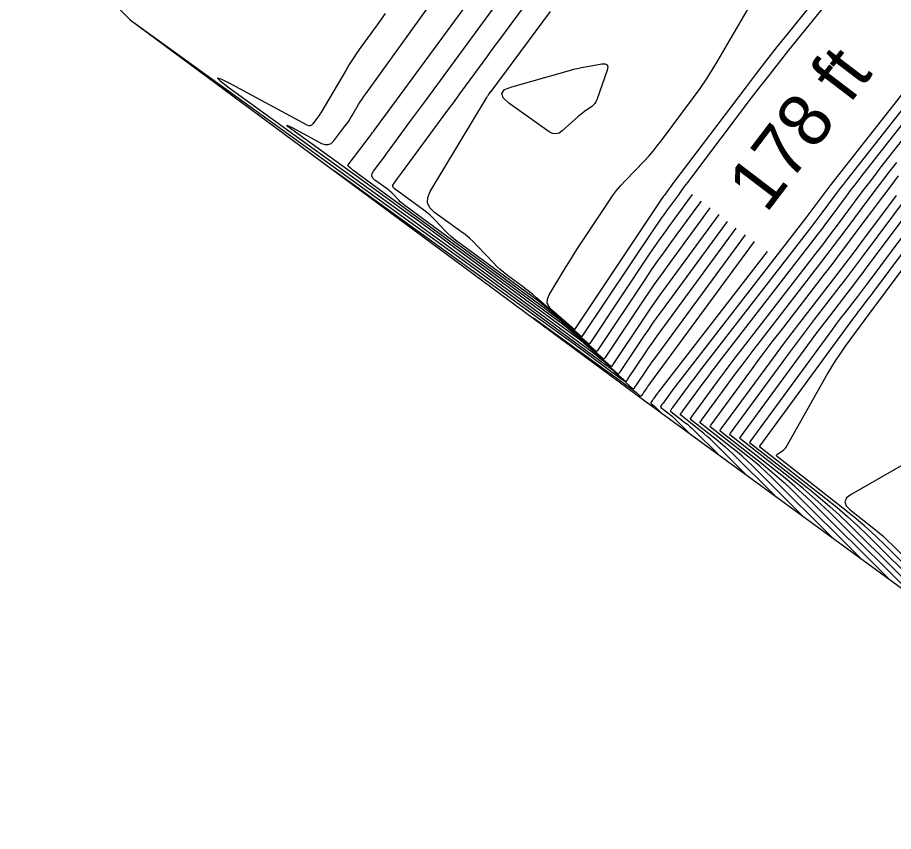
# Model space of a CAD drawing. Extents: x 7585033 to 7595090, y 547091 to 553471.
# Drawn here: x 7586349.7 to 7586454.1, y 547283 to 547380 of the extents above; entities that cross this region are included whole.
import ezdxf

# ---------------------------------------------------------------- set-up
doc = ezdxf.new("R2010")
doc.units = 0
for name, color, linetype in [('E_TERR_BNDRY_Perimeter', 7, 'Continuous'), ('E_TERR_DSPLAY_GeneralTx', 7, 'Continuous'), ('E_TERR_DSPLAY_MajContour', 7, 'Continuous'), ('E_TERR_DSPLAY_MinContour', 7, 'Continuous')]:
    doc.layers.add(name, color=color, linetype=linetype)

msp = doc.modelspace()

# ---------------------------------------------------------------- linework, layer by layer
at = {"layer": 'E_TERR_BNDRY_Perimeter'}
msp.add_lwpolyline([(7586507.86, 547596.21), (7586495.55, 547580.23), (7586483.33, 547564.27), (7586468.31, 547544.88), (7586458.94, 547532.34), (7586446.63, 547516.23), (7586434.88, 547500.79), (7586392.64, 547487.4), (7586380.44, 547481.39), (7586375.31, 547475.38), (7586349.66, 547424.97), (7586351.68, 547391.19), (7586363.11, 547379.7), (7586424.46, 547334.33), (7586496.39, 547281.87), (7586525.63, 547263.53), (7586582.63, 547204.01), (7586615.09, 547187.11), (7586630.91, 547181.81), (7586662.02, 547163.71), (7586688.76, 547131.86)], dxfattribs=at)
at = {"layer": 'E_TERR_DSPLAY_MajContour'}
for points in [[(7586436.55, 547325.51), (7586432.64, 547329.38), (7586432.27, 547329.74), (7586431.89, 547330.08), (7586431.5, 547330.42), (7586431.1, 547330.74), (7586428.73, 547332.59), (7586428.7, 547332.62), (7586428.69, 547332.65), (7586428.69, 547332.69), (7586428.71, 547332.72), (7586428.81, 547332.87), (7586428.84, 547332.9), (7586428.87, 547332.94), (7586428.89, 547332.97), (7586428.92, 547333.01), (7586431.54, 547336.58), (7586431.99, 547337.19), (7586432.44, 547337.79), (7586432.9, 547338.39), (7586433.35, 547338.99), (7586444.54, 547353.43), (7586445.04, 547354.08), (7586445.54, 547354.74), (7586446.03, 547355.4), (7586446.53, 547356.06), (7586448.5, 547358.7), (7586448.99, 547359.36), (7586449.49, 547360.01), (7586449.99, 547360.67), (7586450.5, 547361.32), (7586470.52, 547386.8)], [(7586430.11, 547358.9), (7586429.55, 547358.15), (7586427.28, 547355.04), (7586426.71, 547354.26), (7586426.15, 547353.48), (7586425.6, 547352.68), (7586425.06, 547351.89), (7586417.88, 547341.16), (7586417.87, 547341.14), (7586417.86, 547341.13), (7586417.85, 547341.12), (7586417.85, 547341.1), (7586417.81, 547341.05), (7586417.8, 547341.04), (7586417.79, 547341.04), (7586417.78, 547341.04), (7586417.76, 547341.05), (7586413.7, 547344.6), (7586413.01, 547345.19), (7586412.31, 547345.76), (7586411.6, 547346.32), (7586410.87, 547346.87), (7586402.05, 547353.35), (7586401.69, 547353.62), (7586401.35, 547353.91), (7586401.02, 547354.22), (7586400.7, 547354.54), (7586399.46, 547355.85), (7586399.15, 547356.17), (7586398.81, 547356.47), (7586398.47, 547356.76), (7586398.11, 547357.03), (7586394.58, 547359.59), (7586394.45, 547359.71), (7586394.4, 547359.84), (7586394.41, 547359.99), (7586394.5, 547360.14), (7586394.98, 547360.79), (7586395.1, 547360.95), (7586395.22, 547361.11), (7586395.34, 547361.27), (7586395.46, 547361.43), (7586400.42, 547368.18), (7586401.08, 547369.09), (7586401.75, 547369.99), (7586402.41, 547370.89), (7586403.07, 547371.79), (7586405.72, 547375.4), (7586406.39, 547376.31), (7586407.05, 547377.21), (7586407.72, 547378.11), (7586408.38, 547379.01), (7586411.83, 547383.66)], [(7586393.49, 547380.46), (7586393.01, 547379.79), (7586392.53, 547379.12), (7586390.6, 547376.44), (7586390.12, 547375.76), (7586389.66, 547375.08), (7586389.22, 547374.38), (7586388.79, 547373.68), (7586385.81, 547368.62), (7586385.7, 547368.45), (7586385.59, 547368.27), (7586385.47, 547368.1), (7586385.34, 547367.94), (7586384.83, 547367.28), (7586384.7, 547367.15), (7586384.55, 547367.08), (7586384.39, 547367.08), (7586384.21, 547367.15), (7586375.13, 547372.02), (7586373.93, 547372.63), (7586373.49, 547372.77), (7586373.81, 547372.43), (7586374.88, 547371.62), (7586396.17, 547356.26), (7586398.44, 547354.62), (7586400.7, 547352.97), (7586402.96, 547351.32), (7586405.22, 547349.67), (7586418.06, 547340.23), (7586418.4, 547339.97), (7586418.74, 547339.71), (7586419.06, 547339.44), (7586419.39, 547339.16), (7586421.25, 547337.53), (7586421.28, 547337.51), (7586421.31, 547337.51), (7586421.34, 547337.52), (7586421.36, 547337.55), (7586421.46, 547337.68), (7586421.49, 547337.71), (7586421.51, 547337.74), (7586421.53, 547337.78), (7586421.56, 547337.81), (7586424.43, 547342.1), (7586424.92, 547342.83), (7586425.42, 547343.55), (7586425.92, 547344.26), (7586426.44, 547344.97), (7586434.31, 547355.69)], [(7586462.59, 547361.93), (7586451.62, 547347.2), (7586451.43, 547346.95), (7586451.24, 547346.7), (7586451.05, 547346.45), (7586450.86, 547346.2), (7586450.09, 547345.2), (7586449.9, 547344.95), (7586449.71, 547344.7), (7586449.52, 547344.45), (7586449.33, 547344.2), (7586438.13, 547328.92), (7586438.11, 547328.89), (7586438.11, 547328.88), (7586438.11, 547328.88), (7586438.11, 547328.88), (7586438.11, 547328.88), (7586446.03, 547322.68), (7586447.33, 547321.63), (7586448.6, 547320.54), (7586449.84, 547319.42), (7586451.05, 547318.26), (7586463.73, 547305.69)], [(7586454.4, 547358.79), (7586450.18, 547353.11), (7586449.29, 547351.92), (7586448.38, 547350.72), (7586447.48, 547349.53), (7586446.56, 547348.35), (7586442.9, 547343.62), (7586441.99, 547342.43), (7586441.08, 547341.24), (7586440.19, 547340.04), (7586439.3, 547338.84), (7586433.52, 547330.96), (7586433.5, 547330.92), (7586433.47, 547330.88), (7586433.41, 547330.8), (7586433.4, 547330.79), (7586433.4, 547330.77), (7586433.4, 547330.75), (7586433.42, 547330.73), (7586438.56, 547326.71), (7586439.41, 547326.02), (7586440.25, 547325.31), (7586441.06, 547324.58), (7586441.85, 547323.82), (7586450.14, 547315.6)]]:
    msp.add_lwpolyline(points, dxfattribs=at)
at = {"layer": 'E_TERR_DSPLAY_MinContour'}
for points in [[(7586472.3, 547392.75), (7586446.51, 547359.92), (7586446.26, 547359.61), (7586446.02, 547359.29), (7586445.78, 547358.97), (7586445.54, 547358.66), (7586444.59, 547357.38), (7586444.35, 547357.06), (7586444.12, 547356.75), (7586443.87, 547356.43), (7586443.63, 547356.12), (7586428.52, 547336.59), (7586428.32, 547336.33), (7586428.12, 547336.07), (7586427.92, 547335.81), (7586427.72, 547335.54), (7586426.62, 547334.03), (7586426.59, 547333.99), (7586426.55, 547333.94), (7586426.52, 547333.9), (7586426.49, 547333.86), (7586426.36, 547333.68), (7586426.34, 547333.64), (7586426.33, 547333.6), (7586426.35, 547333.56), (7586426.38, 547333.52), (7586427.37, 547332.76), (7586427.54, 547332.61), (7586427.71, 547332.47), (7586427.88, 547332.31), (7586428.04, 547332.16), (7586429.75, 547330.46)], [(7586471.41, 547389.77), (7586448.5, 547360.62), (7586448.13, 547360.14), (7586447.75, 547359.65), (7586447.39, 547359.17), (7586447.02, 547358.68), (7586445.56, 547356.72), (7586445.19, 547356.23), (7586444.83, 547355.74), (7586444.46, 547355.26), (7586444.08, 547354.77), (7586430.94, 547337.79), (7586430.61, 547337.36), (7586430.28, 547336.93), (7586429.95, 547336.5), (7586429.63, 547336.06), (7586427.77, 547333.52), (7586427.74, 547333.48), (7586427.71, 547333.44), (7586427.68, 547333.4), (7586427.65, 547333.36), (7586427.54, 547333.2), (7586427.51, 547333.16), (7586427.51, 547333.12), (7586427.52, 547333.09), (7586427.56, 547333.06), (7586429.23, 547331.75), (7586429.52, 547331.52), (7586429.8, 547331.27), (7586430.08, 547331.03), (7586430.34, 547330.77), (7586433.15, 547327.98)], [(7586432.21, 547357.3), (7586432.12, 547357.18), (7586427.39, 547350.73), (7586426.58, 547349.62), (7586425.79, 547348.51), (7586425.01, 547347.38), (7586424.25, 547346.25), (7586419.72, 547339.48), (7586419.7, 547339.46), (7586419.69, 547339.44), (7586419.67, 547339.41), (7586419.65, 547339.39), (7586419.59, 547339.3), (7586419.57, 547339.28), (7586419.55, 547339.27), (7586419.53, 547339.28), (7586419.51, 547339.29), (7586416.54, 547341.88), (7586416.04, 547342.31), (7586415.52, 547342.74), (7586415, 547343.15), (7586414.47, 547343.55), (7586389.65, 547361.78), (7586389.62, 547361.81), (7586389.6, 547361.83), (7586389.57, 547361.86), (7586389.54, 547361.88), (7586389.44, 547361.99), (7586389.42, 547362.01), (7586389.39, 547362.04), (7586389.36, 547362.06), (7586389.33, 547362.09), (7586389.11, 547362.25), (7586389.07, 547362.28), (7586389.06, 547362.32), (7586389.06, 547362.36), (7586389.09, 547362.41), (7586391.74, 547365.93), (7586391.87, 547366.1), (7586392, 547366.27), (7586392.13, 547366.45), (7586392.26, 547366.62), (7586392.77, 547367.32), (7586393.03, 547367.67), (7586393.29, 547368.02), (7586408.86, 547389.23)], [(7586448.3, 547386.55), (7586441.45, 547378.05), (7586440.2, 547376.48), (7586438.96, 547374.9), (7586437.73, 547373.32), (7586436.52, 547371.73), (7586427.9, 547360.35), (7586427.76, 547360.16), (7586427.62, 547359.97), (7586427.48, 547359.78), (7586427.34, 547359.59), (7586426.78, 547358.83), (7586426.64, 547358.64), (7586426.51, 547358.45), (7586426.37, 547358.26), (7586426.24, 547358.06), (7586416.05, 547342.83), (7586416.04, 547342.82), (7586416.03, 547342.8), (7586416.03, 547342.8), (7586416.02, 547342.8), (7586416.02, 547342.8), (7586416.02, 547342.8), (7586413.34, 547345.14), (7586412.99, 547345.55), (7586412.82, 547345.98), (7586412.85, 547346.44), (7586413.06, 547346.94), (7586415.02, 547350.22), (7586415.46, 547350.93), (7586415.9, 547351.64), (7586416.35, 547352.34), (7586416.81, 547353.04), (7586420.15, 547358.08), (7586420.61, 547358.74), (7586421.09, 547359.37), (7586421.61, 547359.98), (7586422.15, 547360.57), (7586424.36, 547362.88), (7586424.91, 547363.46), (7586425.43, 547364.06), (7586425.94, 547364.68), (7586426.43, 547365.31), (7586430.27, 547370.46), (7586431.06, 547371.54), (7586431.81, 547372.64), (7586432.53, 547373.77), (7586433.21, 547374.91), (7586437.36, 547382.07)], [(7586433.26, 547356.5), (7586426.91, 547347.85), (7586426.25, 547346.94), (7586425.61, 547346.03), (7586424.97, 547345.11), (7586424.34, 547344.18), (7586420.64, 547338.65), (7586420.62, 547338.62), (7586420.6, 547338.59), (7586420.58, 547338.56), (7586420.56, 547338.53), (7586420.47, 547338.42), (7586420.45, 547338.4), (7586420.43, 547338.39), (7586420.41, 547338.4), (7586420.38, 547338.41), (7586417.97, 547340.52), (7586417.55, 547340.88), (7586417.13, 547341.22), (7586416.7, 547341.56), (7586416.26, 547341.89), (7586397.25, 547355.86), (7586395.64, 547357.04), (7586394.03, 547358.22), (7586392.41, 547359.39), (7586390.8, 547360.56), (7586382.38, 547366.64), (7586381.9, 547367), (7586381.76, 547367.15), (7586381.96, 547367.09), (7586382.5, 547366.82), (7586385.89, 547364.99), (7586386.31, 547364.84), (7586386.69, 547364.84), (7586387.04, 547364.99), (7586387.36, 547365.3), (7586388.7, 547367.03), (7586388.93, 547367.33), (7586389.15, 547367.65), (7586389.36, 547367.97), (7586389.56, 547368.29), (7586390.33, 547369.61), (7586390.53, 547369.93), (7586390.74, 547370.25), (7586390.95, 547370.57), (7586391.17, 547370.88), (7586400.72, 547384.14)], [(7586469.63, 547383.83), (7586452.49, 547362.02), (7586451.86, 547361.2), (7586451.22, 547360.38), (7586450.6, 547359.55), (7586449.97, 547358.72), (7586447.5, 547355.39), (7586446.87, 547354.56), (7586446.25, 547353.74), (7586445.62, 547352.91), (7586444.99, 547352.09), (7586435.77, 547340.19), (7586435.18, 547339.42), (7586434.6, 547338.65), (7586434.02, 547337.88), (7586433.45, 547337.1), (7586430.07, 547332.5), (7586430.05, 547332.47), (7586430.02, 547332.43), (7586430, 547332.4), (7586429.98, 547332.37), (7586429.88, 547332.24), (7586429.87, 547332.21), (7586429.87, 547332.18), (7586429.88, 547332.15), (7586429.9, 547332.13), (7586432.96, 547329.73), (7586433.48, 547329.32), (7586433.98, 547328.89), (7586434.47, 547328.45), (7586434.94, 547327.99), (7586439.95, 547323.03)], [(7586431.16, 547358.1), (7586430.66, 547357.42), (7586427.52, 547353.14), (7586426.74, 547352.07), (7586425.98, 547350.99), (7586425.22, 547349.9), (7586424.48, 547348.8), (7586418.8, 547340.32), (7586418.79, 547340.3), (7586418.78, 547340.28), (7586418.76, 547340.26), (7586418.75, 547340.25), (7586418.7, 547340.18), (7586418.68, 547340.16), (7586418.67, 547340.16), (7586418.65, 547340.16), (7586418.64, 547340.17), (7586415.12, 547343.24), (7586414.52, 547343.75), (7586413.91, 547344.25), (7586413.3, 547344.73), (7586412.67, 547345.21), (7586395.85, 547357.57), (7586395.66, 547357.71), (7586395.47, 547357.87), (7586395.3, 547358.04), (7586395.12, 547358.21), (7586394.45, 547358.92), (7586394.28, 547359.09), (7586394.1, 547359.26), (7586393.92, 547359.41), (7586393.72, 547359.56), (7586392.26, 547360.62), (7586392.01, 547360.85), (7586391.91, 547361.11), (7586391.93, 547361.38), (7586392.1, 547361.68), (7586393.12, 547363.03), (7586393.37, 547363.36), (7586393.61, 547363.69), (7586393.86, 547364.02), (7586394.1, 547364.35), (7586396.44, 547367.54), (7586396.92, 547368.19), (7586397.39, 547368.83), (7586397.86, 547369.47), (7586398.33, 547370.11), (7586407.21, 547382.21)], [(7586446.94, 547382.72), (7586441.59, 547376.08), (7586440.46, 547374.67), (7586439.35, 547373.25), (7586438.24, 547371.83), (7586437.15, 547370.4), (7586429.88, 547360.79), (7586429.52, 547360.31), (7586429.16, 547359.83), (7586428.8, 547359.35), (7586428.45, 547358.87), (7586427.03, 547356.94), (7586426.68, 547356.45), (7586426.33, 547355.96), (7586425.99, 547355.47), (7586425.65, 547354.97), (7586416.96, 547341.99), (7586416.96, 547341.99), (7586416.95, 547341.98), (7586416.95, 547341.97), (7586416.94, 547341.96), (7586416.92, 547341.93), (7586416.91, 547341.92), (7586416.9, 547341.92), (7586416.9, 547341.92), (7586416.89, 547341.93), (7586411.55, 547346.59), (7586411.14, 547346.94), (7586410.71, 547347.29), (7586410.28, 547347.63), (7586409.84, 547347.96), (7586408.07, 547349.26), (7586407.64, 547349.59), (7586407.22, 547349.95), (7586406.82, 547350.32), (7586406.43, 547350.71), (7586404.47, 547352.78), (7586404.01, 547353.24), (7586403.53, 547353.69), (7586403.02, 547354.11), (7586402.5, 547354.5), (7586399.38, 547356.76), (7586398.83, 547357.29), (7586398.56, 547357.89), (7586398.57, 547358.54), (7586398.87, 547359.24), (7586405.62, 547370.47), (7586405.67, 547370.54), (7586405.71, 547370.61), (7586405.76, 547370.68), (7586405.81, 547370.75), (7586406.11, 547371.16), (7586406.12, 547371.16), (7586413.19, 547380.7)], [(7586363.69, 547379.27), (7586404.12, 547350.1), (7586405.75, 547348.92), (7586407.37, 547347.73), (7586409, 547346.55), (7586410.62, 547345.36), (7586419.86, 547338.57), (7586420.1, 547338.39), (7586420.34, 547338.2), (7586420.58, 547338), (7586420.81, 547337.8), (7586422.13, 547336.66), (7586422.16, 547336.63), (7586422.19, 547336.63), (7586422.22, 547336.64), (7586422.25, 547336.67), (7586422.37, 547336.82), (7586422.39, 547336.86), (7586422.42, 547336.9), (7586422.45, 547336.93), (7586422.47, 547336.97), (7586424.52, 547340.03), (7586424.87, 547340.55), (7586425.23, 547341.07), (7586425.59, 547341.58), (7586425.96, 547342.09), (7586435.36, 547354.89)], [(7586443.34, 547320.55), (7586437.24, 547326.6), (7586436.66, 547327.16), (7586436.07, 547327.7), (7586435.46, 547328.22), (7586434.83, 547328.73), (7586431.07, 547331.66), (7586431.05, 547331.69), (7586431.04, 547331.71), (7586431.05, 547331.74), (7586431.06, 547331.76), (7586431.14, 547331.87), (7586431.16, 547331.9), (7586431.18, 547331.93), (7586431.2, 547331.96), (7586431.22, 547331.99), (7586435.36, 547337.63), (7586436.06, 547338.57), (7586436.76, 547339.52), (7586437.47, 547340.45), (7586438.19, 547341.39), (7586445.44, 547350.75), (7586446.2, 547351.74), (7586446.96, 547352.73), (7586447.71, 547353.73), (7586448.46, 547354.73), (7586451.45, 547358.74), (7586452.2, 547359.74), (7586452.96, 547360.74), (7586453.72, 547361.73), (7586454.49, 547362.72)], [(7586467.13, 547303.21), (7586453.19, 547317.03), (7586451.96, 547318.21), (7586450.69, 547319.36), (7586449.4, 547320.47), (7586448.07, 547321.54), (7586440.26, 547327.65), (7586440.16, 547327.75), (7586440.14, 547327.84), (7586440.18, 547327.93), (7586440.29, 547328.01), (7586440.86, 547328.34), (7586441, 547328.43), (7586441.12, 547328.54), (7586441.23, 547328.66), (7586441.32, 547328.8), (7586446.25, 547337.51), (7586446.74, 547338.36), (7586447.26, 547339.19), (7586447.81, 547340.01), (7586448.38, 547340.81), (7586451.84, 547345.53), (7586451.85, 547345.55), (7586451.86, 547345.57), (7586451.88, 547345.58), (7586451.89, 547345.6), (7586451.94, 547345.66), (7586451.95, 547345.67), (7586451.96, 547345.69), (7586451.97, 547345.71), (7586451.98, 547345.72), (7586464.89, 547363.06)], [(7586436.42, 547354.09), (7586425.49, 547339.21), (7586425.26, 547338.9), (7586425.04, 547338.59), (7586424.83, 547338.27), (7586424.61, 547337.96), (7586423.39, 547336.14), (7586423.36, 547336.09), (7586423.33, 547336.05), (7586423.3, 547336.01), (7586423.27, 547335.96), (7586423.14, 547335.79), (7586423.11, 547335.76), (7586423.08, 547335.75), (7586423.04, 547335.75), (7586423, 547335.78), (7586422.24, 547336.45), (7586422.09, 547336.57), (7586421.95, 547336.68), (7586421.8, 547336.8), (7586421.65, 547336.91), (7586416.03, 547341.05), (7586415.04, 547341.77), (7586414.05, 547342.5), (7586413.06, 547343.22), (7586412.06, 547343.93), (7586387.43, 547361.71)], [(7586446.74, 547318.07), (7586439.55, 547325.21), (7586438.86, 547325.87), (7586438.16, 547326.51), (7586437.44, 547327.12), (7586436.7, 547327.72), (7586432.25, 547331.2), (7586432.23, 547331.22), (7586432.22, 547331.24), (7586432.22, 547331.26), (7586432.23, 547331.28), (7586432.3, 547331.38), (7586432.32, 547331.4), (7586432.34, 547331.43), (7586432.36, 547331.45), (7586432.37, 547331.47), (7586437.27, 547338.15), (7586438.09, 547339.27), (7586438.92, 547340.38), (7586439.76, 547341.48), (7586440.61, 547342.58), (7586445.89, 547349.4), (7586446.78, 547350.56), (7586447.67, 547351.73), (7586448.55, 547352.9), (7586449.43, 547354.07), (7586452.93, 547358.76), (7586453.81, 547359.94), (7586454.69, 547361.1)], [(7586460.28, 547360.79), (7586451.26, 547348.68), (7586450.9, 547348.19), (7586450.53, 547347.7), (7586450.16, 547347.22), (7586449.79, 547346.73), (7586448.29, 547344.81), (7586447.92, 547344.32), (7586447.55, 547343.84), (7586447.19, 547343.35), (7586446.82, 547342.86), (7586436.98, 547329.43), (7586436.96, 547329.4), (7586436.93, 547329.37), (7586436.93, 547329.36), (7586436.93, 547329.35), (7586436.93, 547329.35), (7586436.94, 547329.34), (7586444.16, 547323.69), (7586445.35, 547322.73), (7586446.51, 547321.74), (7586447.64, 547320.71), (7586448.75, 547319.65), (7586460.33, 547308.16)], [(7586456.94, 547310.64), (7586446.45, 547321.04), (7586445.45, 547322), (7586444.42, 547322.93), (7586443.37, 547323.83), (7586442.29, 547324.7), (7586435.76, 547329.81), (7586435.76, 547329.81), (7586435.75, 547329.82), (7586435.75, 547329.84), (7586435.76, 547329.85), (7586435.8, 547329.91), (7586435.83, 547329.94), (7586444.32, 547341.52), (7586444.85, 547342.25), (7586445.4, 547342.97), (7586445.94, 547343.69), (7586446.5, 547344.41), (7586448.71, 547347.27), (7586449.27, 547347.99), (7586449.81, 547348.71), (7586450.36, 547349.43), (7586450.9, 547350.16), (7586457.98, 547359.66)], [(7586453.54, 547313.12), (7586444.15, 547322.43), (7586443.25, 547323.29), (7586442.33, 547324.12), (7586441.39, 547324.93), (7586440.43, 547325.71), (7586434.59, 547330.27), (7586434.58, 547330.28), (7586434.57, 547330.3), (7586434.58, 547330.31), (7586434.58, 547330.33), (7586434.64, 547330.4), (7586434.66, 547330.44), (7586434.68, 547330.45), (7586441.81, 547340.18), (7586442.52, 547341.14), (7586443.24, 547342.1), (7586443.97, 547343.06), (7586444.7, 547344.01), (7586447.64, 547347.81), (7586448.37, 547348.76), (7586449.1, 547349.72), (7586449.82, 547350.67), (7586450.54, 547351.64), (7586455.88, 547358.81)], [(7586437.47, 547353.29), (7586425.02, 547336.33), (7586424.94, 547336.22), (7586424.86, 547336.11), (7586424.78, 547336), (7586424.7, 547335.88), (7586424.31, 547335.3), (7586424.28, 547335.25), (7586424.24, 547335.2), (7586424.21, 547335.15), (7586424.17, 547335.11), (7586424.03, 547334.92), (7586424, 547334.88), (7586423.96, 547334.86), (7586423.92, 547334.87), (7586423.87, 547334.9), (7586423.66, 547335.09), (7586423.61, 547335.13), (7586423.56, 547335.17), (7586423.5, 547335.21), (7586423.45, 547335.25), (7586421.43, 547336.74), (7586421.08, 547337), (7586420.72, 547337.26), (7586420.37, 547337.51), (7586420.01, 547337.77), (7586411.17, 547344.15)], [(7586439.03, 547352.1), (7586426.1, 547335.4), (7586426.03, 547335.3), (7586425.96, 547335.21), (7586425.89, 547335.11), (7586425.82, 547335.02), (7586425.47, 547334.54), (7586425.43, 547334.5), (7586425.4, 547334.45), (7586425.36, 547334.4), (7586425.33, 547334.35), (7586425.19, 547334.16), (7586425.16, 547334.11), (7586425.16, 547334.07), (7586425.17, 547334.03), (7586425.21, 547333.99), (7586425.5, 547333.76), (7586425.56, 547333.71), (7586425.62, 547333.66), (7586425.68, 547333.6), (7586425.74, 547333.55), (7586426.36, 547332.94)], [(7586458.28, 547328.43), (7586449.06, 547323.17), (7586448.51, 547322.74), (7586448.31, 547322.29), (7586448.44, 547321.82), (7586448.93, 547321.32), (7586451.55, 547319.27), (7586452.19, 547318.75), (7586452.82, 547318.21), (7586453.44, 547317.65), (7586454.04, 547317.08), (7586470.53, 547300.73)]]:
    msp.add_lwpolyline(points, dxfattribs=at)
msp.add_lwpolyline([(7586418.61, 547369.94), (7586418.48, 547369.73), (7586418.31, 547369.55), (7586418.12, 547369.38), (7586417.27, 547368.78), (7586417.06, 547368.63), (7586416.85, 547368.47), (7586416.65, 547368.31), (7586416.46, 547368.14), (7586414.61, 547366.47), (7586414.23, 547366.21), (7586413.84, 547366.11), (7586413.45, 547366.17), (7586413.04, 547366.38), (7586408.25, 547369.79), (7586407.57, 547370.41), (7586407.4, 547370.94), (7586407.74, 547371.39), (7586408.59, 547371.74), (7586415.47, 547373.68), (7586415.95, 547373.81), (7586416.42, 547373.92), (7586416.9, 547374.02), (7586417.38, 547374.12), (7586419.31, 547374.46), (7586419.72, 547374.48), (7586419.96, 547374.36), (7586420.04, 547374.1), (7586419.96, 547373.71), (7586418.72, 547370.18)], close=True, dxfattribs=at)

# ---------------------------------------------------------------- texts
at = {"layer": 'E_TERR_DSPLAY_GeneralTx'}
msp.add_text('178 ft', height=6.3, rotation=52.6971, dxfattribs=at).set_placement((7586438.92, 547356.54))

doc.saveas('drawing.dxf')
